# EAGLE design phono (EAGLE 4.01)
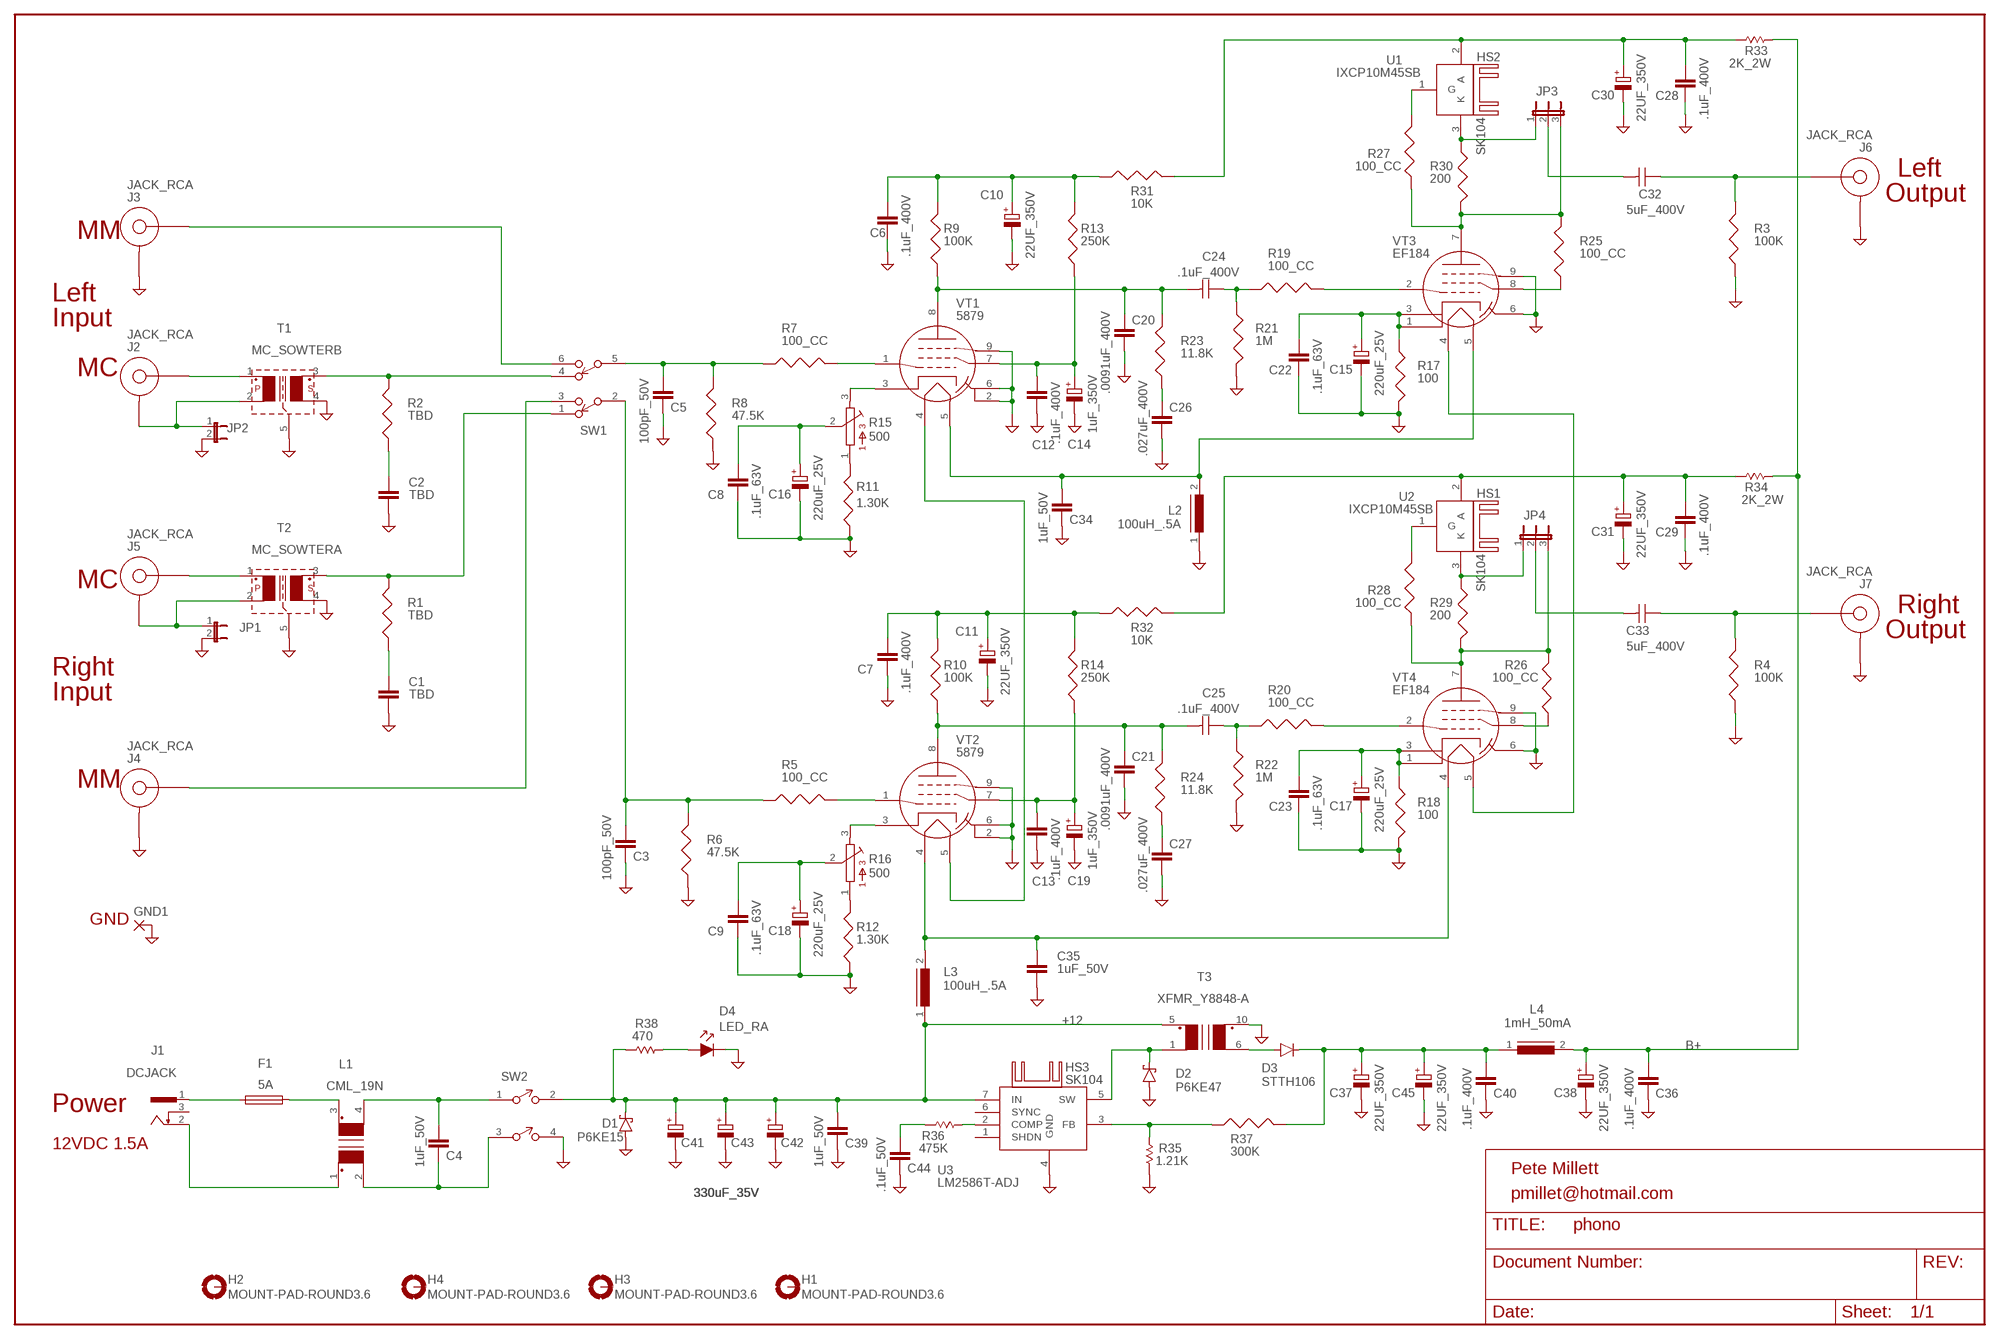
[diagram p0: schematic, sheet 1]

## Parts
C1  TBD  C-EU050-075X075  [C050-075X075]
C2  TBD  C-EU050-075X075  [C050-075X075]
C3  100pF_50V  C-EU050-045X075  [C050-045X075]
C4  1uF_50V  C-EU050-030X075  [C050-030X075]
C5  100pF_50V  C-EU050-045X075  [C050-045X075]
C6  .1uF_400V  C-EU150-064X183  [C150-064X183]
C7  .1uF_400V  C-EU150-064X183  [C150-064X183]
C8  .1uF_63V  C-EU050-075X075  [C050-075X075]
C9  .1uF_63V  C-EU050-075X075  [C050-075X075]
C10  22UF_350V  CPOL-EUE5-13  [E5-13]
C11  22UF_350V  CPOL-EUE5-13  [E5-13]
C12  .1uF_400V  C-EU150-064X183  [C150-064X183]
C13  .1uF_400V  C-EU150-064X183  [C150-064X183]
C14  1uF_350V  CPOL-EUE5-10.5  [E5-10,5]
C15  220uF_25V  CPOL-EUE5-13  [E5-13]
C16  220uF_25V  CPOL-EUE5-13  [E5-13]
C17  220uF_25V  CPOL-EUE5-13  [E5-13]
C18  220uF_25V  CPOL-EUE5-13  [E5-13]
C19  1uF_350V  CPOL-EUE5-10.5  [E5-10,5]
C20  .0091uF_400V  C-EU050-045X075  [C050-045X075]
C21  .0091uF_400V  C-EU050-045X075  [C050-045X075]
C22  .1uF_63V  C-EU050-075X075  [C050-075X075]
C23  .1uF_63V  C-EU050-075X075  [C050-075X075]
C24  .1uF_400V  CCAP_P1..  [CCAP_P1]
C25  .1uF_400V  CCAP_P1..  [CCAP_P1]
C26  .027uF_400V  C-EU102-043X133  [C102-043X133]
C27  .027uF_400V  C-EU102-043X133  [C102-043X133]
C28  .1uF_400V  C-EU150-064X183  [C150-064X183]
C29  .1uF_400V  C-EU150-064X183  [C150-064X183]
C30  22UF_350V  CPOL-EUE5-13  [E5-13]
C31  22UF_350V  CPOL-EUE5-13  [E5-13]
C32  5uF_400V  CCAP_5-8  [CCAP_5-8]
C33  5uF_400V  CCAP_5-8  [CCAP_5-8]
C34  1uF_50V  C-EU050-030X075  [C050-030X075]
C35  1uF_50V  C-EU050-030X075  [C050-030X075]
C36  .1uF_400V  C-EU150-064X183  [C150-064X183]
C37  22UF_350V  CPOL-EUE5-13  [E5-13]
C38  22UF_350V  CPOL-EUE5-13  [E5-13]
C39  1uF_50V  C-EU050-030X075  [C050-030X075]
C40  .1uF_400V  C-EU150-064X183  [C150-064X183]
C41  330uF_35V  CPOL-EUE5-10.5  [E5-10,5]
C42  330uF_35V  CPOL-EUE5-10.5  [E5-10,5]
C43  330uF_35V  CPOL-EUE5-10.5  [E5-10,5]
C44  .1uF_50V  C-EU025-030X050  [C025-030X050]
C45  22UF_350V  CPOL-EUE5-13  [E5-13]
D1  P6KE15  P6KEXX  [CB417-15]
D2  P6KE47  P6KEXX  [CB417-15]
D3  STTH106  UF4003  [DO41-10]
D4  LED_RA  [LED_RA]
F1  5A  PICOFUSE  [PICOFUSE]
GND1  3,81/1,4  [3,81/1,4]
H1  MOUNT-PAD-ROUND3.6  [3,6-PAD]
H2  MOUNT-PAD-ROUND3.6  [3,6-PAD]
H3  MOUNT-PAD-ROUND3.6  [3,6-PAD]
H4  MOUNT-PAD-ROUND3.6  [3,6-PAD]
HS1  SK104  [SK104]
HS2  SK104  [SK104]
HS3  SK104  [SK104]
J1  DCJACK  [DCJACK]
J2  JACK_RCA  [JACK_RCA]
J3  JACK_RCA  [JACK_RCA]
J4  JACK_RCA  [JACK_RCA]
J5  JACK_RCA  [JACK_RCA]
J6  JACK_RCA  [JACK_RCA]
J7  JACK_RCA  [JACK_RCA]
JP1  JP1E  [JP1]
JP2  JP1E  [JP1]
JP3  JP2E  [JP2]
JP4  JP2E  [JP2]
L1  CML_19N  [CML_19N]
L2  100uH_.5A  B82133  [SUKW3-27]
L3  100uH_.5A  B82133  [SUKW3-27]
L4  1mH_50mA  B82133  [SUKW3-27]
R1  TBD  R1/2W  [R1/2W]
R2  TBD  R1/2W  [R1/2W]
R3  100K  R1/2W  [R1/2W]
R4  100K  R1/2W  [R1/2W]
R5  100_CC  R1/2W  [R1/2W]
R6  47.5K  R1/2W  [R1/2W]
R7  100_CC  R1/2W  [R1/2W]
R8  47.5K  R1/2W  [R1/2W]
R9  100K  R1/2W  [R1/2W]
R10  100K  R1/2W  [R1/2W]
R11  1.30K  R1/2W  [R1/2W]
R12  1.30K  R1/2W  [R1/2W]
R13  250K  R1/2W  [R1/2W]
R14  250K  R1/2W  [R1/2W]
R15  500  B25P  [B25P]
R16  500  B25P  [B25P]
R17  100  R1/2W  [R1/2W]
R18  100  R1/2W  [R1/2W]
R19  100_CC  R1/2W  [R1/2W]
R20  100_CC  R1/2W  [R1/2W]
R21  1M  R1/2W  [R1/2W]
R22  1M  R1/2W  [R1/2W]
R23  11.8K  R1/2W  [R1/2W]
R24  11.8K  R1/2W  [R1/2W]
R25  100_CC  R1/2W  [R1/2W]
R26  100_CC  R1/2W  [R1/2W]
R27  100_CC  R1/2W  [R1/2W]
R28  100_CC  R1/2W  [R1/2W]
R29  200  R1/2W  [R1/2W]
R30  200  R1/2W  [R1/2W]
R31  10K  R1/2W  [R1/2W]
R32  10K  R1/2W  [R1/2W]
R33  2K_2W  R2W_5083  [R2W_5083]
R34  2K_2W  R2W_5083  [R2W_5083]
R35  1.21K  R1/4W  [R1/4W]
R36  475K  R1/4W  [R1/4W]
R37  300K  R1/2W  [R1/2W]
R38  470  R1/4W  [R1/4W]
SW1  SW_DPDT_TA  [SW_DPDT_TA]
SW2  SW_DPST_P227  [SW_DPST_P227]
T1  MC_SOWTERB  [MC_SOWTER_B]
T2  MC_SOWTERA  [MC_SOWTER_A]
T3  XFMR_Y8848-A  [Y8848-A]
U1  IXCP10M45SB  [TO220B]
U2  IXCP10M45SB  [TO220B]
U3  LM2586T-ADJ  [TO220-7]
VT1  5879  [NOVAL_PCB]
VT2  5879  [NOVAL_PCB]
VT3  EF184  [NOVAL_PCB]
VT4  EF184  [NOVAL_PCB]

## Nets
+12: C39.2 C41.+ C42.+ C43.+ D1.K(C) L3.1 R38.1 SW2.2 T3.5(S1) U3.7(IN)
B+: C36.2 C38.+ L4.2 R33.P$2 R34.P$2
FIL+: C35.2 L3.2 VT2.4 VT4.4
FIL-: C34.2 L2.2 VT1.5 VT3.5
GND: C1.1 C2.1 C3.1 C5.1 C6.1 C7.1 C8.1 C9.1 C10.- C11.- C12.1 C13.1 C14.- C15.- C16.- C17.- C18.- C19.- C20.1 C21.1 C22.1 C23.1 C26.1 C27.1 C28.1 C29.1 C30.- C31.- C34.1 C35.1 C36.1 C37.- C38.- C39.1 C40.1 C41.- C42.- C43.- C44.1 C45.- D1.A D2.A D4.P$1(K) GND1.1(P) J3.P$1 J4.P$1 J6.P$1 J7.P$1 JP1.2 JP2.2 L2.1 R3.P$1 R4.P$1 R6.P$1 R8.P$1 R11.P$1 R12.P$1 R17.P$2 R18.P$2 R21.P$2 R22.P$2 R35.1 SW2.4 T1.4 T1.5 T2.4 T2.5 T3.10(P1) U3.4(GND) VT1.2 VT1.6 VT1.9 VT2.2 VT2.6 VT2.9 VT3.6 VT3.9 VT4.6 VT4.9
HS2: JP4.3 R26.P$2 R28.P$1 R29.P$2 VT4.7
N$1: C28.2 C30.+ R31.P$2 R33.P$1 U1.2(A)
N$2: C6.2 C10.+ R9.P$2 R13.P$2 R31.P$1
N$3: R19.P$2 VT3.2
N$4: R25.P$1 VT3.8
N$5: R2.P$2 SW1.4 T1.3
N$6: C15.+ C22.2 R17.P$1 VT3.1 VT3.3
N$7: R11.P$2 R15.1
N$8: R7.P$2 VT1.1
N$9: C5.2 R7.P$1 R8.P$2 SW1.5
N$10: C7.2 C11.+ R10.P$2 R14.P$2 R32.P$1
N$11: R15.3 VT1.3
N$12: C26.2 R23.P$1
N$13: C8.2 C16.+ R15.2
N$14: C24.P$2 R19.P$1 R21.P$1
N$15: JP4.1 R29.P$1 U2.3(K)
N$16: C25.P$2 R20.P$1 R22.P$1
N$17: JP3.1 R30.P$1 U1.3(K)
N$18: C32.P$1 JP3.2
N$19: J2.P$1 JP2.1 T1.2
N$20: VT1.4 VT2.5
N$21: C37.+ C40.2 C45.+ D3.K(C) L4.1 R37.P$2
N$22: JP3.3 R25.P$2 R27.P$1 R30.P$2 VT3.7
N$23: C17.+ C23.2 R18.P$1 VT4.1 VT4.3
N$24: R5.P$2 VT2.1
N$25: C12.2 C14.+ R13.P$1 VT1.7
N$26: C3.2 R5.P$1 R6.P$2 SW1.2
N$27: C13.2 C19.+ R14.P$1 VT2.7
N$28: R20.P$2 VT4.2
N$29: C33.P$1 JP4.2
N$30: J5.P$1 JP1.1 T2.2
N$31: C33.P$2 J7.P$2 R4.P$2
N$32: C21.2 C25.P$1 R10.P$1 R24.P$2 VT2.8
N$33: J5.P$2 T2.1
N$34: F1.1 J1.1
N$35: R27.P$2 U1.1(G)
N$36: C27.2 R24.P$1
N$37: C32.P$2 J6.P$2 R3.P$2
N$38: C4.2 L1.4(S2) SW2.1
N$39: R12.P$2 R16.1
N$40: J2.P$2 T1.1
N$41: C20.2 C24.P$1 R9.P$1 R23.P$2 VT1.8
N$42: R1.P$2 SW1.1 T2.3
N$43: R16.3 VT2.3
N$44: R36.2 U3.2(COMP)
N$45: D2.K(C) T3.1(S2) U3.5(SW)
N$46: D4.P$2(A) R38.2
N$47: D3.A T3.6(P2)
N$48: R35.2 R37.P$1 U3.3(FB)
N$49: C44.2 R36.1
N$50: C9.2 C18.+ R16.2
N$51: J3.P$2 SW1.6
N$52: J4.P$2 SW1.3
N$53: J1.2 L1.1
N$54: C4.1 L1.2 SW2.3
N$56: R26.P$1 VT4.8
N$57: C29.2 C31.+ R32.P$2 R34.P$1 U2.2(A)
N$59: F1.2 L1.3(S1)
N$60: VT3.4 VT4.5
N$61: C2.2 R2.P$1
N$62: C1.2 R1.P$1
N$63: R28.P$2 U2.1(G)
Unconnected: H1.B3,6(MOUNT) H2.B3,6(MOUNT) H3.B3,6(MOUNT) H4.B3,6(MOUNT) J1.3 U3.1(SHDN) U3.6(SYNC)

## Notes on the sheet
- Left
- Output
- MM
- Left
- Input
- MC
- MC
- Right
- Output
- Right
- Input
- MM
- GND
- Power
- 12VDC 1.5A
- Pete Millett
- pmillet@hotmail.com

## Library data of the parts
C1-C9 C12 C13 C20-C23 C26-C29 C34-C36 C39 C40 C44 = rcl:C-EU: CAPACITOR, European symbol
C10 C11 C14-C19 C30 C31 C37 C38 C41-C43 C45 = rcl:CPOL-EU: POLARIZED CAPACITOR, European symbol
C24 C25 = wheat:CCAP_P1: COUPLING CAP, .1UF SOLEN, AURICAP
C32 C33 = wheat:CCAP_5-8: COUPLING CAP, 5-8UF SOLEN, 5UF AURICAP, ETC.
D1 D2 = diode:P6KEXX: DIODE
D3 = diode:UF4003: DIODE
D4 = wheat:LED_RA: RA LED 3MM
F1 = fuse:PICOFUSE: PICOFUSE
GND1 = wirepad:3,81/1,4: THROUGH-HOLE PAD
H1-H4 = holes:MOUNT-PAD-ROUND: MOUNTING PAD, round
HS1-HS3 = heatsink:SK104: HEATSINK
J1 = wheat:DCJACK: DC POWER JACK, 2.5mm/5.5mm CUI-STACK PJ-102B
J2-J7 = wheat:JACK_RCA: SINGLE RCA JACK, CUI RCJ-04X
JP1 JP2 = jumper:JP1E: JUMPER
JP3 JP4 = jumper:JP2E: JUMPER
L1 = wheat:CML_19N: PANASONIC CML 19N TYPE
L2-L4 = inductors:B82133: INDUCTOR
R1-R14 R17-R32 R37 = wheat:R1/2W: RESISTOR, 1/2W THM
R15 R16 = pot:B25P: POTENTIOMETER
R33 R34 = wheat:R2W_5083: RES, 2W METAL FILM, BC 5083NW
R35 R36 R38 = wheat:R1/4W: RESISTOR, 1/4W THM
SW1 = wheat:SW_DPDT_TA: SWITCH, DPDT, E-SWITCH TA-SERIES
SW2 = wheat:SW_DPST_P227: SWITCH, DPST, POWER, E-SWITCH P227 TA-SERIES
T1 T2 = wheat:MC_SOWTER: SOWTER MC XFMR
T3 = wheat:XFMR_Y8848-A: FLYBACK TRANSFORMER COILCRAFT Y8848-A
U1 U2 = wheat:IXCP10M45S: IXYS CCS IXCP10M45S TO220
U3 = wheat:LM2586T-ADJ: LM2586T-ADJ SW REG (NATIONAL)
VT1 VT2 = wheat:5879: 5879 PENTODE
VT3 VT4 = wheat:EF184: EF184/6EJ7 pantode

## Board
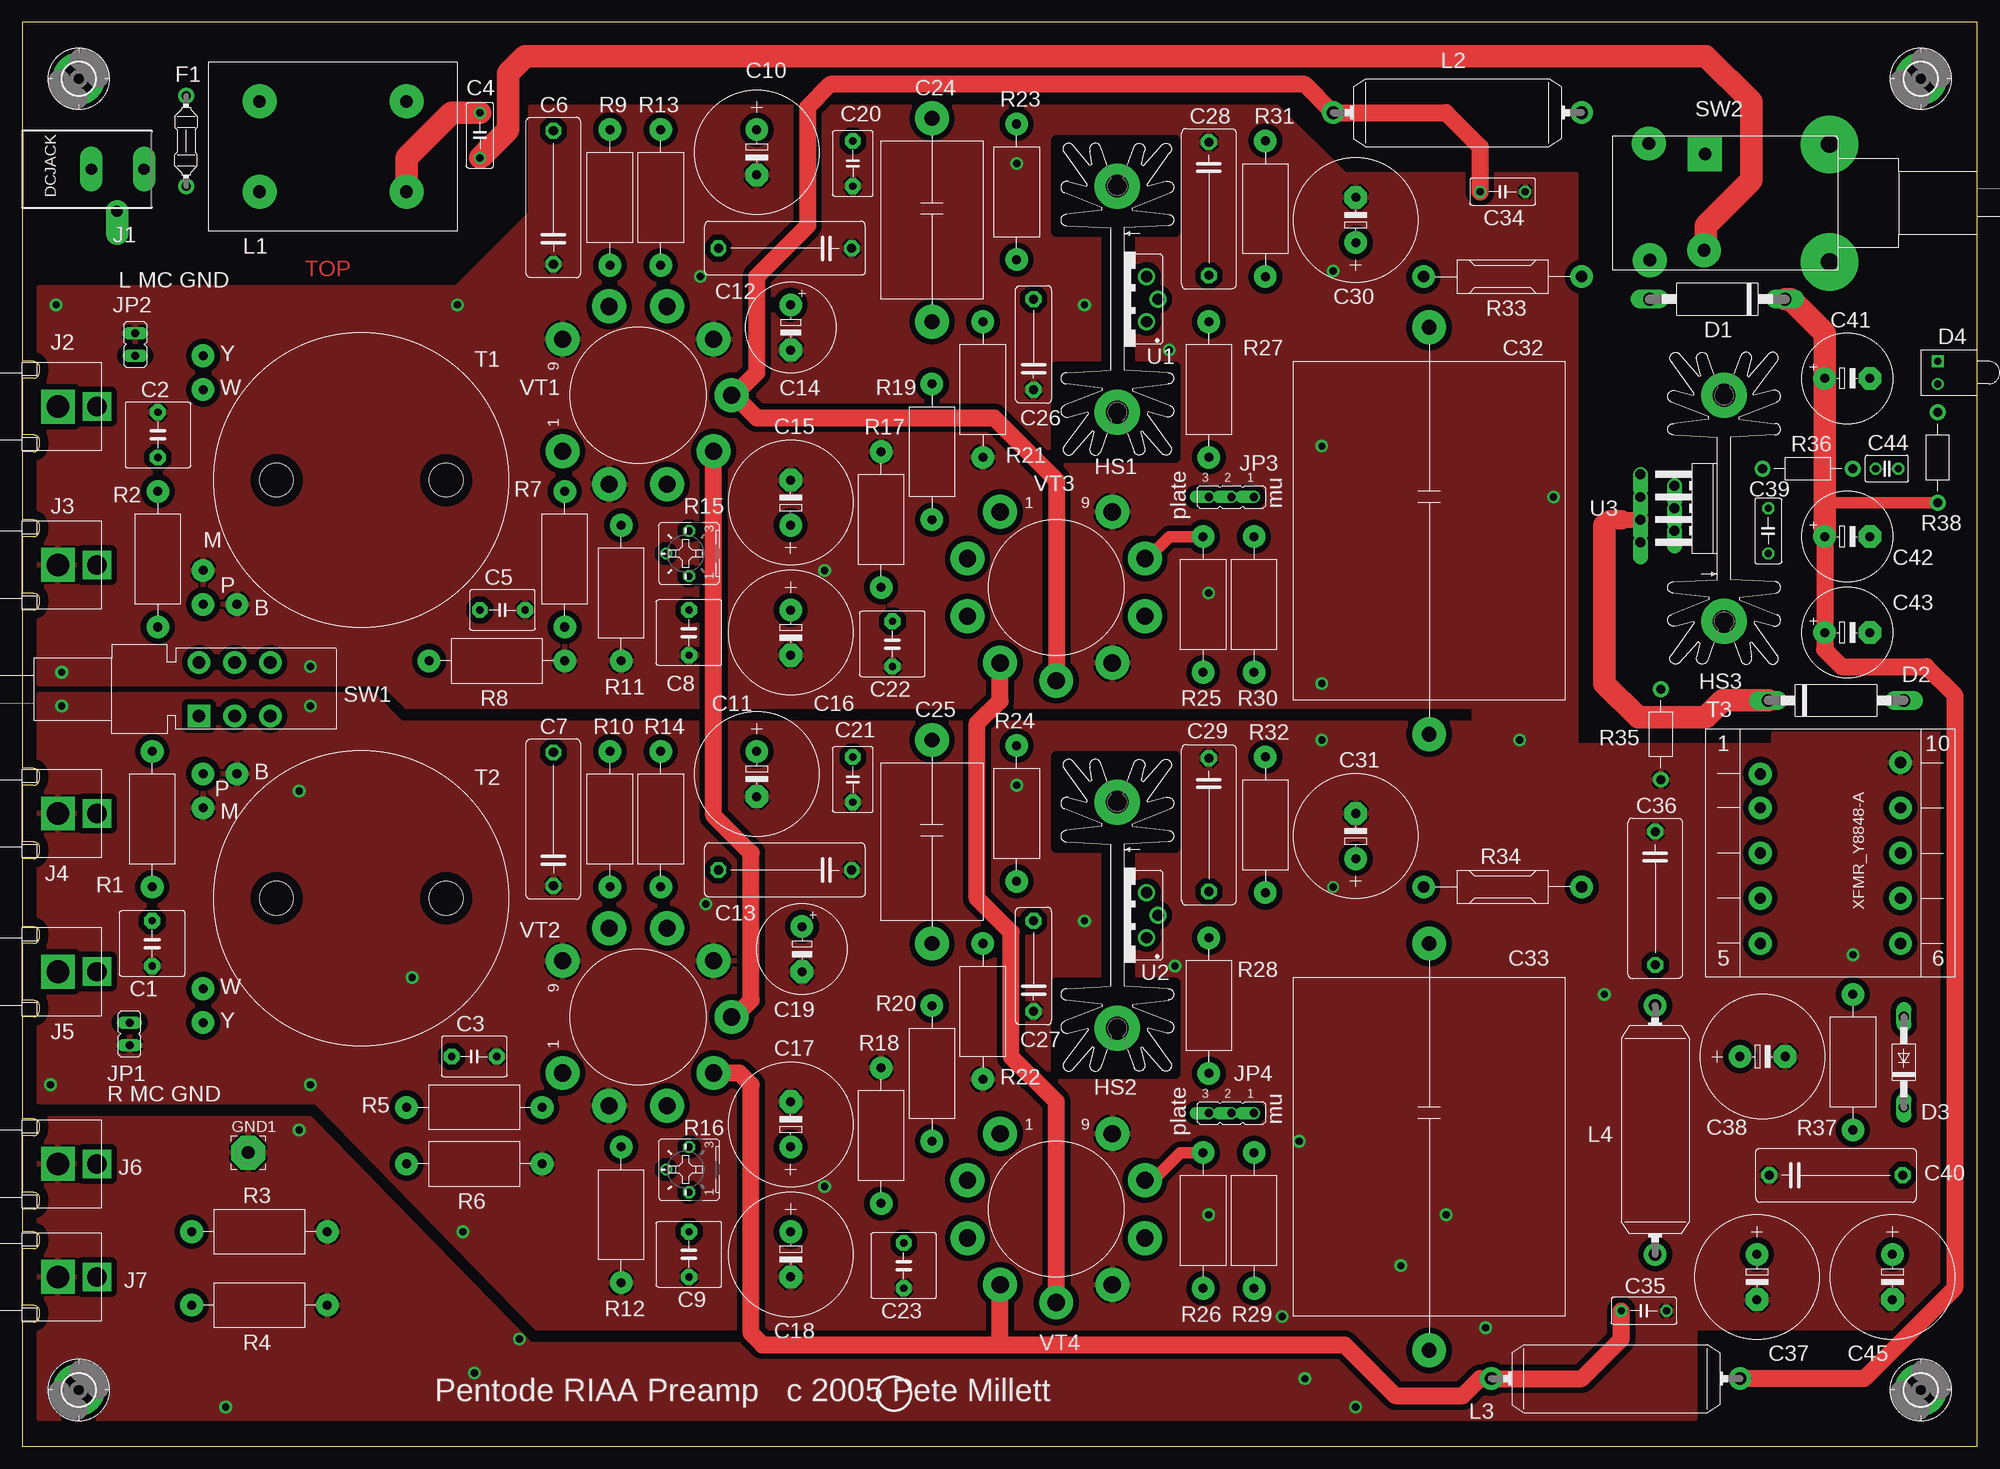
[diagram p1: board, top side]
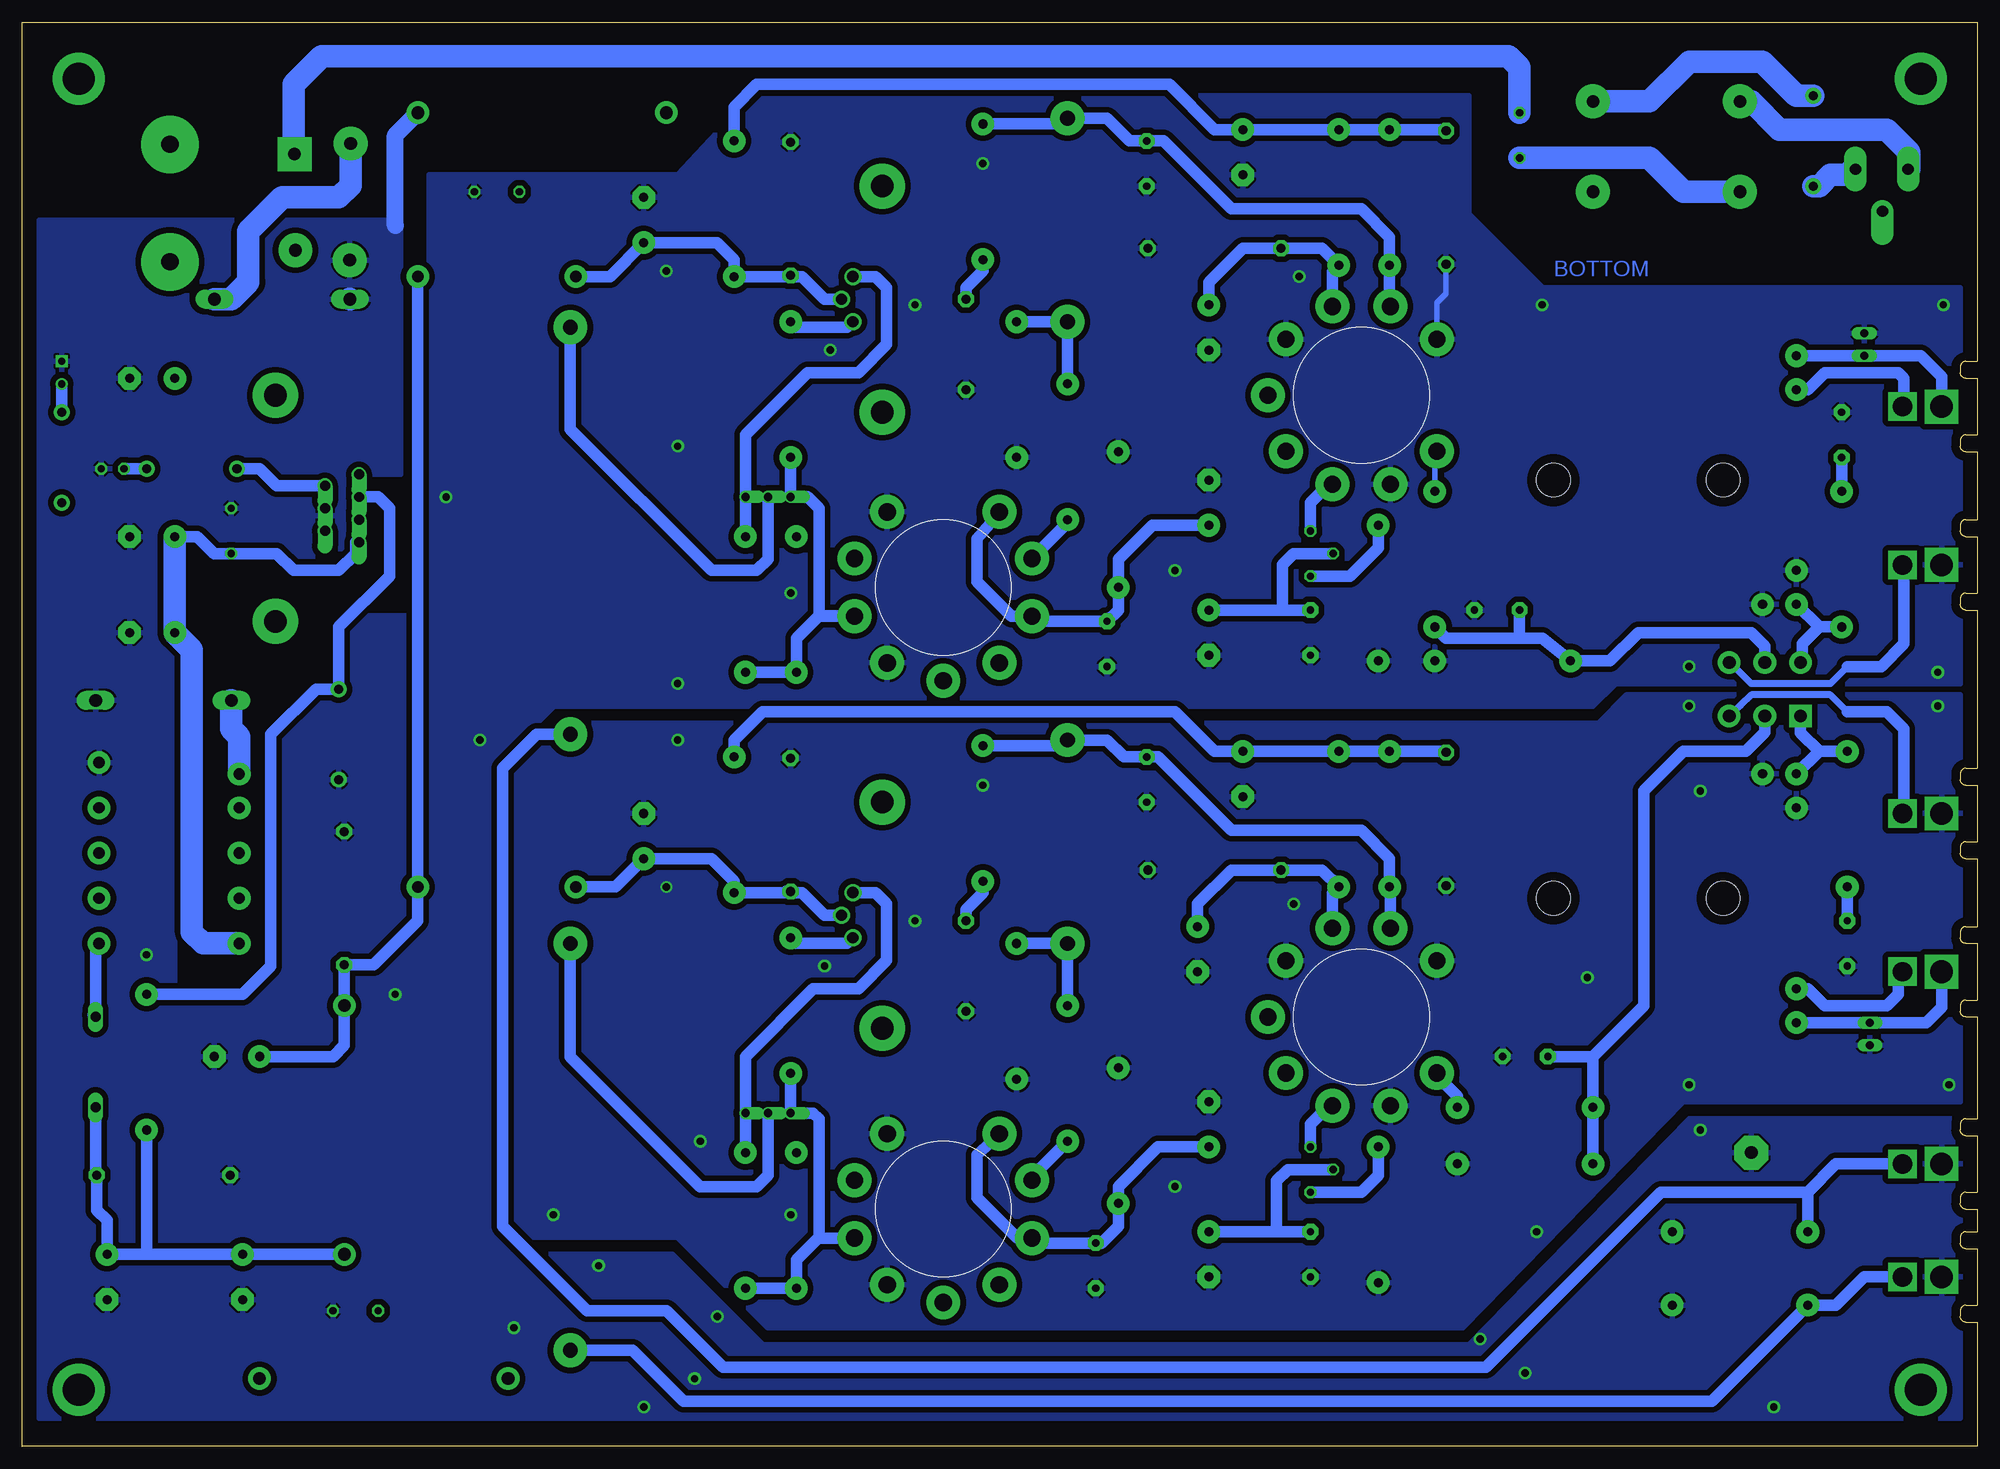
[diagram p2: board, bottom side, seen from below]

Size 219.71 x 160.03 mm. Coordinates in mm from the lower left corner, seen from the top.
Outline: 76 segments
Copper layers used: Top, Bottom
Holes 0.81 mm at 256.31,70.29
Holes 0.91 mm at 256.31,65.21
Holes 1.02 mm at 256.31,60.13
Holes 1.12 mm at 256.31,55.05
Holes 1.27 mm at 256.31,49.97
Holes 1.42 mm at 256.31,44.89
Holes 1.68 mm at 256.31,39.81
Holes 1.93 mm at 256.31,34.73
Holes 2.18 mm at 256.31,29.65
Holes 2.54 mm at 256.31,24.57
Holes 3.6 mm at 256.31,19.49
Holes 3.81 mm at 256.31,14.41

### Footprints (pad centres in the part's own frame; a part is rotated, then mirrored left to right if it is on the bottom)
C050-075X075 = drill 0.813 pad 1.778 octagon: 1 -2.54,0; 2 2.54,0
C050-045X075 = drill 0.813 pad 1.778 octagon: 1 -2.54,0; 2 2.54,0
C050-030X075 = drill 0.813 octagon: 1 -2.54,0; 2 2.54,0
C150-064X183 = drill 1.016 pad 1.778 octagon: 1 -7.493,0; 2 7.493,0
E5-13 = drill 1.016 pad 2.54 round: + -2.54,0 | drill 1.016 pad 2.54 octagon: - 2.54,0
E5-10,5 = drill 1.016 pad 2.54 round: + -2.54,0 | drill 1.016 pad 2.54 octagon: - 2.54,0
CCAP_P1 = drill 1.676 pad 3.81 round: P$1 -11.43,0; P$2 11.43,0
C102-043X133 = drill 1.016 pad 1.778 octagon: 1 -5.08,0; 2 5.08,0
CCAP_5-8 = drill 1.676 pad 3.81 round: P$1 -22.86,0; P$2 22.86,0
C025-030X050 = drill 0.813 octagon: 1 -1.27,0; 2 1.27,0
CB417-15 = drill 1.422 long: A 7.62,0; K -7.62,0
DO41-10 = drill 1.118 long: A 5.08,0; K -5.08,0
LED_RA = drill 0.813 square: P$1 1.27,4.445 | drill 0.813 round: P$2 -1.27,4.445
PICOFUSE = drill 1.016 pad 1.778 round: 1 -5.08,0; 2 5.08,0
3,81/1,4 = drill 1.422 pad 3.81 octagon: 1 0,0
3,6-PAD = drill 3.6 pad 5.842 round: B3,6 0,0
SK104 = drill 2.54 pad 5.08 round: A2,5 -12.7,-0.762; B2,5 12.7,-0.762
DCJACK = drill 1.27 pad 2.54 long: 1 0,13.694; 2 0,7.778 | drill 1.27 pad 2.54 offset: 3 4.732,10.659
JACK_RCA = drill 2.54 pad 3.81 square: P$1 0,-4.013 | drill 2.184 square: P$2 0,-8.382
JP1 = drill 0.914 long: 1 0,-1.27; 2 0,1.27
JP2 = drill 0.914 offset: 1 -2.54,0; 2 0,0; 3 2.54,0
CML_19N = drill 1.422 pad 3.81 round: 1 -8.255,5.08; 2 -8.255,-5.08; 3 8.255,5.08; 4 8.255,-5.08
SUKW3-27 = drill 1.422 pad 2.54 round: 1 -13.97,0; 2 13.97,0
R1/2W = drill 1.016 pad 2.54 round: P$1 0,0; P$2 15.24,0
B25P = drill 0.813 octagon: 1 -2.54,0; 2 0,2.54; 3 2.54,0
R2W_5083 = drill 1.27 pad 2.54 round: P$1 -8.89,0; P$2 8.89,0
R1/4W = drill 1.016 pad 1.778 round: 1 0,0; 2 10.16,0
SW_DPDT_TA = drill 1.422 pad 2.54 square: 1 -18.6,3 | drill 1.422 pad 2.54 round: 2 -22.6,3; 3 -26.6,3; 4 -18.6,-3; 5 -22.6,-3; 6 -26.6,-3
SW_DPST_P227 = drill 1.422 pad 3.81 square: 1 -30.6,5.5 | drill 1.422 pad 3.81 round: 2 -36.9,6.7; 3 -30.7,-5.3; 4 -36.8,-6.4 | drill 1.93 pad 6.452 round: 5 -16.6,6.6; 6 -16.6,-6.6
MC_SOWTER_B = drill 1.016 pad 2.54 round: 1 -17.78,10.16; 2 -17.78,13.97; 3 -17.78,-13.97; 4 -17.78,-10.16; 5 -13.97,-13.97 | hole 3.81: -9.525,0; 9.525,0
MC_SOWTER_A = drill 1.016 pad 2.54 round: 1 -17.78,-10.16; 2 -17.78,-13.97; 3 -17.78,13.97; 4 -17.78,10.16; 5 -13.97,13.97 | hole 3.81: -9.525,0; 9.525,0
Y8848-A = drill 1.27 pad 2.54 round: 1 -7.874,8.89; 2 -7.874,5.08; 3 -7.874,0; 4 -7.874,-5.08; 5 -7.874,-10.16; 6 7.874,-10.16; 7 7.874,-5.08; 8 7.874,0; 9 7.874,5.08; 10 7.874,10.16
TO220B = drill 1.27 round: 1 -2.54,0; 2 0,-1.27; 3 2.54,0
TO220-7 = drill 1.118 pad 1.626 offset: 1 -3.81,-8.636; 2 -2.54,-4.826; 3 -1.27,-8.636; 4 0,-4.826; 5 1.27,-8.636; 6 2.54,-4.826; 7 3.81,-8.636
NOVAL_PCB = drill 1.93 pad 3.81 round: 1 6.299,-8.484; 2 9.982,-3.251; 3 9.982,3.251; 4 6.299,8.484; 5 0,10.49; 6 -6.299,8.484; 7 -9.982,3.251; 8 -9.982,-3.251; 9 -6.299,-8.484

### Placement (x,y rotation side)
C1  14.61,56.53 90 top
C2  15.24,113.68 270 top
C3  50.8,43.83 180 top
C4  51.44,147.33 90 top
C5  53.98,93.99 180 top
C6  59.69,140.35 90 top
C7  59.69,70.5 90 top
C8  74.93,91.45 90 top
C9  74.93,21.6 90 top
C10  82.55,145.43 270 top
C11  82.55,75.58 270 top
C12  85.72,134.63 180 top
C13  85.72,64.78 180 top
C14  86.36,125.74 270 top
C15  86.36,106.06 90 top
C16  86.36,91.45 270 top
C17  86.36,36.21 90 top
C18  86.36,21.6 270 top
C19  87.63,55.89 270 top
C20  93.34,144.16 90 top
C21  93.34,74.94 90 top
C22  97.79,90.18 90 top
C23  99.06,20.33 90 top
C24  102.23,137.81 270 top
C25  102.23,67.96 270 top
C26  113.67,123.84 90 top
C27  113.67,53.99 90 top
C28  133.35,139.08 270 top
C29  133.35,69.86 270 top
C30  149.86,137.81 90 top
C31  149.86,68.59 90 top
C32  158.12,102.88 270 top
C33  158.12,33.67 270 top
C34  166.37,140.98 180 top
C35  182.25,15.25 180 top
C36  183.51,61.61 270 top
C37  194.94,19.06 270 top
C38  195.58,43.83 0 top
C39  196.22,102.88 270 top
C40  203.84,30.49 0 top
C41  205.1,120.03 0 top
C42  205.1,102.25 0 top
C43  205.1,91.45 0 top
C44  209.55,109.87 180 top
C45  210.19,19.06 270 top
D1  190.5,128.92 180 top
D2  203.84,83.83 0 top
D3  211.46,43.19 90 top
D4  219.71,120.66 90 top
F1  18.41,146.7 90 top
GND1  25.4,33.03 0 top
H1  6.35,153.68 0 top
H2  6.35,6.36 0 top
H3  213.36,153.68 0 top
H4  213.36,6.36 0 top
HS1  123.83,128.92 270 top
HS2  123.83,59.7 270 top
HS3  190.5,105.42 90 top
J1  0,143.52 270 top
J2  0,116.85 90 top
J3  0,99.07 90 top
J4  0,71.13 90 top
J5  0,53.35 90 top
J6  0,31.76 90 top
J7  0,19.06 90 top
JP1  12.06,46.37 180 top
JP2  12.7,123.84 0 top
JP3  135.89,106.69 180 top
JP4  135.89,37.48 180 top
L1  34.92,146.06 0 top
L2  161.29,149.87 180 top
L3  179.07,7.63 180 top
L4  183.51,35.57 90 top
R1  14.61,62.88 90 top
R2  15.24,107.33 270 top
R3  34.29,24.14 180 top
R4  34.29,15.89 180 top
R5  43.18,38.11 0 top
R6  58.42,31.76 180 top
R7  60.96,92.09 90 top
R8  60.96,88.28 180 top
R9  66.04,132.73 90 top
R10  66.04,62.88 90 top
R11  67.31,88.28 90 top
R12  67.31,18.43 90 top
R13  71.75,132.73 90 top
R14  71.75,62.88 90 top
R15  74.93,100.34 90 top
R16  74.93,31.13 90 top
R17  96.52,96.53 90 top
R18  96.52,27.32 90 top
R19  102.23,119.39 270 top
R20  102.23,49.54 270 top
R21  107.95,126.38 270 top
R22  107.95,56.53 270 top
R23  111.76,133.36 90 top
R24  111.76,63.51 90 top
R25  132.72,102.25 270 top
R26  132.72,33.03 270 top
R27  133.35,111.14 90 top
R28  133.35,41.92 90 top
R29  138.43,33.03 270 top
R30  138.43,102.25 270 top
R31  139.7,146.7 270 top
R32  139.7,77.48 270 top
R33  166.37,131.46 0 top
R34  166.37,62.88 0 top
R35  184.15,74.94 90 top
R36  205.74,109.87 180 top
R37  205.74,50.81 270 top
R38  215.26,106.06 90 top
SW1  1.27,85.1 180 top
SW2  219.71,139.71 0 top
T1  38.1,108.6 0 top
T2  38.1,61.61 0 top
T3  203.2,66.69 0 top
U1  126.36,128.92 90 top
U2  126.36,59.7 90 top
U3  190.5,105.42 270 top
VT1  69.22,118.12 270 top
VT2  69.22,48.27 270 top
VT3  116.2,96.53 180 top
VT4  116.2,26.68 180 top

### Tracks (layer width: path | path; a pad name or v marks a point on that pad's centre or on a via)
+12
  Top 1.27: 202.56,106.06 R38.1
  Top 1.93: L3.1 207.01,7.63 217.17,17.79 217.17,84.47 214,87.64 204.47,87.64 202.56,89.55 C42.+
  Top 2.54: C42.+ 202.56,106.06 C41.+ 202.56,125.11 198.75,128.92 D1.K
  Bottom 1.27: U3.7 182.25,101.61 182.25,100.34 184.15,98.44 189.23,98.44 191.13,100.34 C39.2 198.12,100.34 200.03,102.25 C42.+
  Bottom 2.54: C42.+ C43.+ 200.66,89.55 200.66,57.8 199.39,56.53 T3.5 | SW2.2 182.81,141.69 184.15,140.35 190.5,140.35 194.31,136.54 194.31,130.82 196.22,128.92 D1.K
B+
  Bottom 1.27: C38.+ 184.78,43.83 183.51,45.1 L4.2 C36.2 180.21,54.11 175.26,59.07 R34.P$2 R33.P$2
FIL+
  Top 1.93: VT2.4 80.59,41.97 81.92,40.65 81.92,12.71 83.19,11.44 109.86,11.44 | VT4.4 109.91,17.84 109.86,17.79 109.86,11.44 | 109.86,11.44 148.59,11.44 154.31,5.73 161.93,5.73 163.83,7.63 | 163.83,7.63 L3.2 | 163.83,7.63 175.26,7.63 179.71,12.08 C35.2
FIL-
  Top 1.93: 80.01,118.12 VT1.5 | 80.01,118.12 82.55,120.66 82.55,131.46 88.27,137.17 88.27,150.51 90.81,153.05 144.15,153.05 L2.2 160.02,149.87 163.83,146.06 C34.2 | VT3.5 116.2,108.6 109.22,115.58 82.55,115.58 80.01,118.12
GND  (via drill 0.81 pad 1.27, 0.81 pad 1.42)
  Bottom 0.61: 66.67,18.43 67.31,17.79 R12.P$1 | C6.1 59.69,129.55 60.73,128.51 VT1.9
  Bottom 1.93: L2.1 177.8,147.33 177.8,137.17
  Bottom 2.54: D1.A 182.91,128.95
  other vias: 50.8,8.27 55.88,12.08 144.15,7.63 141.6,14.62 149.86,4.46 154.94,20.33 164.47,13.35 49.53,24.14 32.38,40.65 31.11,35.57 22.86,4.46 3.17,40.65 4.45,83.2 4.45,87.01 32.38,87.64 32.38,83.2 3.81,128.28 48.9,128.28 146.05,112.41 129.54,53.99 143.51,34.3 168.28,79.39 177.8,50.81 160.02,26.05 31.11,73.67 133.35,95.9 133.35,26.05 146.05,79.39 146.05,85.74 128.91,123.2 172.09,106.69 147.32,132.09 43.81,52.72 90.17,29.22 205.74,55.26 90.17,98.44 147.32,62.88 111.76,74.31 119.38,59.07 119.38,128.28 111.76,144.16 76.2,131.46 76.83,60.97
  pour Top (isolate 0.635): 163.19,13.35 163.19,84.47 174.62,84.47 174.62,78.75 196.85,78.75 196.85,80.02 215.9,80.02 215.9,18.43 210.82,13.35 186.69,13.35 187.32,13.35
  pour Bottom (isolate 0.635): 1.91,3.19 165.74,3.19 165.74,21.6 146.69,21.6 136.53,11.44 57.15,11.44 32.38,36.84 1.91,36.84
  pour Bottom (isolate 0.635): 57.78,13.35 135.89,13.35 146.05,23.51 167.64,23.51 167.64,81.29 42.55,81.29 39.37,84.47 1.91,84.47 1.91,38.75 33.02,38.75
  pour Bottom (isolate 0.635): 1.91,85.74 40.64,85.74 43.18,83.2 160.02,83.2 165.1,78.12 165.1,3.19 217.81,3.19 217.81,137.81 177.16,137.81 177.16,109.23 181.61,109.23 181.61,95.26 202.56,95.26 202.56,50.81 193.04,50.81 193.04,93.36 173.99,93.36 173.99,142.89 146.05,142.89 137.79,151.78 57.15,151.78 57.15,138.44 48.9,130.19 1.91,130.19
  pour Top (isolate 0.635): 174.62,83.2 43.18,83.2 40.64,85.74 1.91,85.74 1.91,130.19 48.9,130.19 57.15,138.44 57.15,150.51 140.97,150.51 148.59,142.89 174.62,142.89
  pour Top (isolate 0.635): 1.91,84.47 39.37,84.47 42.55,81.29 163.19,81.29 163.19,13.35 57.78,13.35 33.02,38.75 1.91,38.75
  pour Top (isolate 0.635): 1.91,36.84 1.91,3.19 187.96,3.19 187.96,13.98 147.96,13.98 147.96,11.44 57.15,11.44 32.38,36.84
HS2
  Bottom 1.27: R29.P$2 R26.P$2 132.72,20.97 130.18,23.51 | VT4.7 130.1,23.43 130.18,23.51 | 130.18,23.51 130.18,36.84 130.81,37.48 JP4.3 R28.P$1
N$1
  Bottom 1.27: R33.P$1 153.67,131.46 C30.+ 141.6,135.27 139.7,133.36 R31.P$2 133.35,131.46 | U1.2 129.54,128.92 132.08,131.46 133.35,131.46 | 133.35,131.46 C28.2
N$2
  Bottom 1.27: R31.P$1 139.7,150.51 137.16,153.05 90.81,153.05 85.72,147.97 C10.+ R13.P$2 R9.P$2 59.69,147.97 C6.2
N$3
  Bottom 1.27: VT3.2 102.23,103.77 R19.P$2
N$4
  Top 1.27: VT3.8 126.44,99.78 128.91,102.25 R25.P$1
N$5
  Bottom 0.61: 19.68,88.28 SW1.4
  Bottom 1.27: 17.78,92.09 R2.P$2 | 17.78,92.09 T1.3 | 17.78,92.09 19.68,90.18 19.68,88.28
N$6
  Bottom 1.27: VT3.1 109.86,104.97 112.39,101.99 112.39,97.17 108.51,93.28 VT3.3 105.66,92.72 C22.2 96.52,93.99 R17.P$1 96.52,99.71 92.71,103.52 C15.+
N$7
  Bottom 1.27: R11.P$2 67.31,100.98 70.48,97.8 R15.1
N$8
  Bottom 0.61: 60.96,111.77 60.91,111.82 VT1.1 60.73,111.37 60.96,111.14 R7.P$2
N$9
  Bottom 0.61: R8.P$2 46.35,88.28
  Bottom 1.27: SW1.5 23.87,89.92 25.4,91.45 38.1,91.45 41.27,88.28 R8.P$2 48.9,90.82 51.44,90.82 | 51.44,90.82 C5.2 | 51.44,90.82 59.69,90.82 R7.P$1
N$10
  Bottom 1.27: C7.2 59.69,78.12 R10.P$2 R14.P$2 | R14.P$2 72.39,78.12 | 72.39,78.12 74.93,78.12 | 72.39,78.12 71.75,77.48 R14.P$2 | R14.P$2 C11.+ 85.72,78.12 90.17,82.56 136.53,82.56 139.7,79.39 R32.P$1
N$11
  Bottom 1.27: VT1.3 72.85,108.14 74.93,106.06 R15.3
N$12
  Bottom 1.27: C26.2 113.67,130.19 111.76,132.09 R23.P$1
N$13
  Bottom 0.61: C8.2 78.11,93.99
  Bottom 1.27: R15.2 76.83,100.34 78.11,99.07 78.11,93.99 | C8.2 C16.+
N$14
  Bottom 1.27: R21.P$1 C24.P$2 102.23,120.03 R19.P$1
N$15
  Bottom 1.27: R29.P$1 JP4.1 138.43,43.83 130.81,51.45 125.73,51.45 122.56,54.62 122.56,60.97 123.83,62.24 U2.3
N$16
  Bottom 1.27: R22.P$1 C25.P$2 R20.P$1
N$17
  Bottom 1.27: R30.P$1 JP3.1 138.43,113.68 131.44,120.66 125.73,120.66 122.56,123.84 122.56,130.19 123.83,131.46 U1.3
N$18
  Bottom 1.27: JP3.2 135.89,99.71 137.16,98.44 142.24,98.44 158.12,114.31 C32.P$1
N$19
  Bottom 1.27: J2.P$1 4.01,120.23 6.35,122.57 JP2.1 T1.2
N$20
  Top 1.93: VT1.4 77.7,70.9 81.92,66.69 81.92,50.18 80.01,48.27 VT2.5
N$21
  Bottom 1.27: D3.K 211.46,30.49 C40.2 211.33,26.56 210.19,25.41 C45.+ 205.74,21.6 | 205.74,21.6 C37.+ L4.1 | 205.74,21.6 R37.P$2
N$22
  Bottom 0.406: VT3.7 126.44,93.28
  Bottom 0.61: 126.44,93.28 126.36,93.36
  Bottom 1.27: 126.44,93.28 130.1,93.28 130.18,93.36 | 126.36,93.36 130.18,93.36 | R30.P$2 R25.P$2 132.72,90.82 130.18,93.36 | R27.P$1 JP3.3 131.44,106.69 130.18,105.42 130.18,93.36
N$23
  Bottom 0.61: VT4.3 106.15,23.51 106.05,23.51
  Bottom 1.27: VT4.1 109.86,35.12 112.39,32.78 112.39,27.95 107.87,23.43 VT4.3 | 106.05,23.51 106.05,22.87 C23.2 98.42,22.87 96.52,24.78 R18.P$1 96.52,29.22 92.08,33.67 C17.+
N$24
  Bottom 0.61: 60.96,41.92 60.91,41.97 VT2.1
  Bottom 1.27: 60.96,41.92 58.42,39.38 R5.P$2
N$25
  Bottom 0.61: 72.39,128.28 72.47,128.21 VT1.7 | 78.11,134.63 C12.2
  Bottom 1.27: VT1.7 72.47,132.02 R13.P$1 73.66,134.63 78.11,134.63 82.55,134.63 86.36,130.82 C14.+
N$26
  Bottom 1.27: SW1.2 23.87,80.28 26.04,78.12 33.02,78.12 37.47,73.67 37.47,49.54 43.18,43.83 | 43.18,43.83 C3.2 | R6.P$2 R5.P$1 43.18,43.83
N$27
  Bottom 0.61: 72.39,58.43 72.47,58.36 VT2.7 | 78.11,64.78 C13.2
  Bottom 1.27: VT2.7 72.47,62.17 R14.P$1 73.66,64.78 78.11,64.78 83.82,64.78 87.63,60.97 C19.+
N$28
  Bottom 0.61: 106.12,29.93 106.05,29.86 106.05,30.49 | R20.P$2 102.23,33.92
  Bottom 1.27: VT4.2 106.12,29.93 | 106.05,30.49 R20.P$2
N$29
  Bottom 1.27: JP4.2 135.89,30.49 137.16,29.22 143.51,29.22 158.12,43.83 C33.P$1
N$30
  Bottom 1.27: J5.P$1 4.01,49.34 5.71,47.64 JP1.1 T2.2
N$31
  Bottom 1.27: C33.P$2 151.13,10.81 145.41,5.09 29.84,5.09 R4.P$2 15.88,15.89 12.7,19.06 J7.P$2 8.26,19.06
N$32
  Bottom 0.61: 65.96,62.8 R10.P$1
  Bottom 1.27: VT2.8 65.96,62.8 | R10.P$1 66.04,66.05 69.22,69.23 83.82,69.23 92.08,77.48 C21.2 95.89,77.48 97.79,79.39 C25.P$1 102.87,78.75 R24.P$2
N$33
  Bottom 0.61: J5.P$2 8.26,53.35 8.89,52.72
  Bottom 1.27: T2.1 19.05,51.45 17.14,49.54 10.16,49.54 8.89,50.81 8.89,52.72
N$34
  Bottom 2.54: F1.1 17.78,141.62 16.51,142.89 14.61,142.89 13.97,143.52 J1.1
N$35
  Bottom 1.27: R27.P$2 132.72,125.74 127,125.74 U1.1
N$36
  Bottom 1.27: C27.2 113.67,60.34 111.76,62.24 R24.P$1
N$37
  Bottom 1.27: J6.P$2 15.88,31.76 19.05,28.59 | 19.05,28.59 R3.P$2 | 19.05,28.59 35.56,28.59 55.24,8.9 140.97,8.9 147.32,15.25 156.21,15.25 165.74,24.78 165.74,76.21 161.93,80.02 C32.P$2
N$38
  Top 2.54: C4.2 48.26,149.87 43.18,144.79 L1.4
  Bottom 2.54: SW2.1 189.11,145.31 189.23,145.43 189.23,153.05 186.06,156.22 52.7,156.22 51.44,154.95 C4.2
N$39
  Bottom 1.27: R12.P$2 67.31,30.49 69.22,28.59 R16.1
N$40
  Bottom 0.61: J2.P$2 8.89,116.85 8.26,117.49
  Bottom 1.27: T1.1 19.05,118.76 17.14,120.66 8.89,120.66 8.26,120.03 8.26,117.49
N$41
  Bottom 0.61: VT1.8 65.96,127.72 66.04,127.65 | 102.87,149.24 C24.P$1 102.23,148.6
  Bottom 1.27: 66.04,127.65 R9.P$1 66.04,135.9 69.22,139.08 83.82,139.08 91.44,146.7 C20.2 95.25,146.7 97.79,149.24 C24.P$1 | R23.P$2 102.23,148.6
N$42
  Bottom 1.27: R1.P$2 17.78,78.12 | SW1.1 19.87,80.21 17.78,78.12 | 17.78,78.12 T2.3
N$43
  Bottom 0.61: 72.85,38.29 VT2.3
  Bottom 1.27: R16.3 74.93,36.21 72.85,38.29
N$44
  Bottom 1.27: U3.2 191.13,107.96 193.04,109.87 R36.2
N$45
  Top 1.778: 179.71,104.15 U3.5
  Top 2.184: 179.71,104.15 178.44,104.15 177.8,103.52
  Top 2.54: 177.8,103.52 177.8,85.74 181.61,81.93 189.23,81.93 191.13,83.83 D2.K
  Bottom 2.54: T3.1 195.33,79.77 196.22,80.66 D2.K
N$46
  Bottom 1.27: R38.2 D4.P$2
N$47
  Bottom 1.27: 211.71,48.53 D3.A 211.46,56.53 T3.6
N$48
  Bottom 1.27: R37.P$1 194.94,50.81 191.77,53.99 191.77,80.02 186.69,85.1 R35.2 184.15,92.09 178.44,97.8 178.44,105.42 179.71,106.69 U3.3
N$49
  Bottom 1.27: R36.1 C44.2
N$50
  Bottom 1.27: 78.74,24.14 C18.+ | R16.2 77.47,31.13 78.74,29.86 78.74,24.14 | C9.2 78.74,24.14
N$51
  Bottom 0.61: 8.26,99.07 J3.P$2
  Bottom 0.813: SW1.6 26.6,86.94 25.4,85.74 16.51,85.74 14.61,87.64
  Bottom 1.27: 14.61,87.64 10.79,87.64 8.26,90.18 8.26,99.07
N$52
  Bottom 0.61: J4.P$2 8.26,71.13
  Bottom 0.813: SW1.3 26.6,83.27 25.4,84.47 16.51,84.47 14.61,82.56
  Bottom 1.27: 14.61,82.56 10.16,82.56 8.26,80.66 8.26,71.13
N$53
  Bottom 2.54: L1.1 25.4,151.14 22.23,147.97 10.16,147.97 7.62,145.43 7.62,143.52 J1.2
N$54
  Top 2.54: 188.59,134 SW2.3 189.23,134.63 189.23,137.17 194.31,142.25 194.31,151.14 189.23,156.22 56.52,156.22 54.61,154.32 54.61,147.97 C4.1
  Bottom 2.54: C4.1 36.83,144.79 33.02,140.98 L1.2
N$56
  Top 1.27: VT4.8 127.08,29.93 130.18,33.03 R26.P$1
N$57
  Bottom 1.27: U2.2 129.54,59.7 132.08,62.24 133.35,62.24 C29.2 133.86,62.37 133.99,62.24 R32.P$2 139.7,63.51 142.24,66.05 C31.+ 153.03,62.88 R34.P$1
N$59
  Bottom 2.54: F1.2 20.32,151.78 24.13,155.59 32.38,155.59 36.83,151.14 L1.3
N$60
  Top 1.93: VT3.4 109.91,83.78 107.31,81.29 107.31,61.61 111.12,57.8 111.12,43.83 116.2,38.75 VT4.5 116.2,15.89
N$61
  Bottom 1.27: R2.P$1 C2.2
N$62
  Bottom 1.27: C1.2 R1.P$1
N$63
  Bottom 1.27: U2.1 127,56.53 132.72,56.53 R28.P$2

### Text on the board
Top: TOP
Bottom: BOTTOM
tNames: L MC GND | mu | plate | R MC GND | mu | plate | Pentode RIAA Preamp c 2005 Pete Millett
Holes: DRILL PLAN | SYM | SIZE | TOL. | CNT | 0.032 in | +/-0.003 in | 81 | 0.036 in | +/-0.003 in | 10 | 0.040 in | +/-0.003 in | 132 | 0.044 in | +/-0.003 in | 9 | 0.050 in | +/-0.003 in | 23 | 0.056 in | +/-0.003 in | 25 | 0.066 in | +/-0.003 in | 8 | 0.076 in | +/-0.003 in | 38 | 0.086 in | +/-0.003 in | 6 | 0.100 in | +/-0.003 in | 12 | 0.142 in | +/-0.003 in | 4 | 0.150 in | +/-0.003 in | 4 | TOTAL | 352 | Drill file will contain one extra of | each drill, placed in above diagram.
Measures: 6.30 | 6.05 | DETAIL A (SCALE 2X) | 5.65 ref | 0.075 | 5.50 ref | 0.03 R MAX TYP | 0.20 | DETAIL A | CL | 6 PLCS | 4.75 ref | 0.20 | 4.60 | 0.075 | 0.075 | 3.90 | 3.35 ref | 2.80 | 2.10 | 1.25 | 0.75 | 0.25 | 0.00 | 0.00 | 0.25 | 8.40 | 8.65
